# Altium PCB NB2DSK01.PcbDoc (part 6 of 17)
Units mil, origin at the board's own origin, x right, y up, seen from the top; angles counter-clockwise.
Board outline 11815 x 6500.03 mil, 8 copper layers (Top Layer, MidLayer1, MidLayer2, GND, PWR, MidLayer3, MidLayer4, Bottom Layer), stack 74.62 mil thick; 798 components, 1002 nets, 3927 pads, 3182 vias.
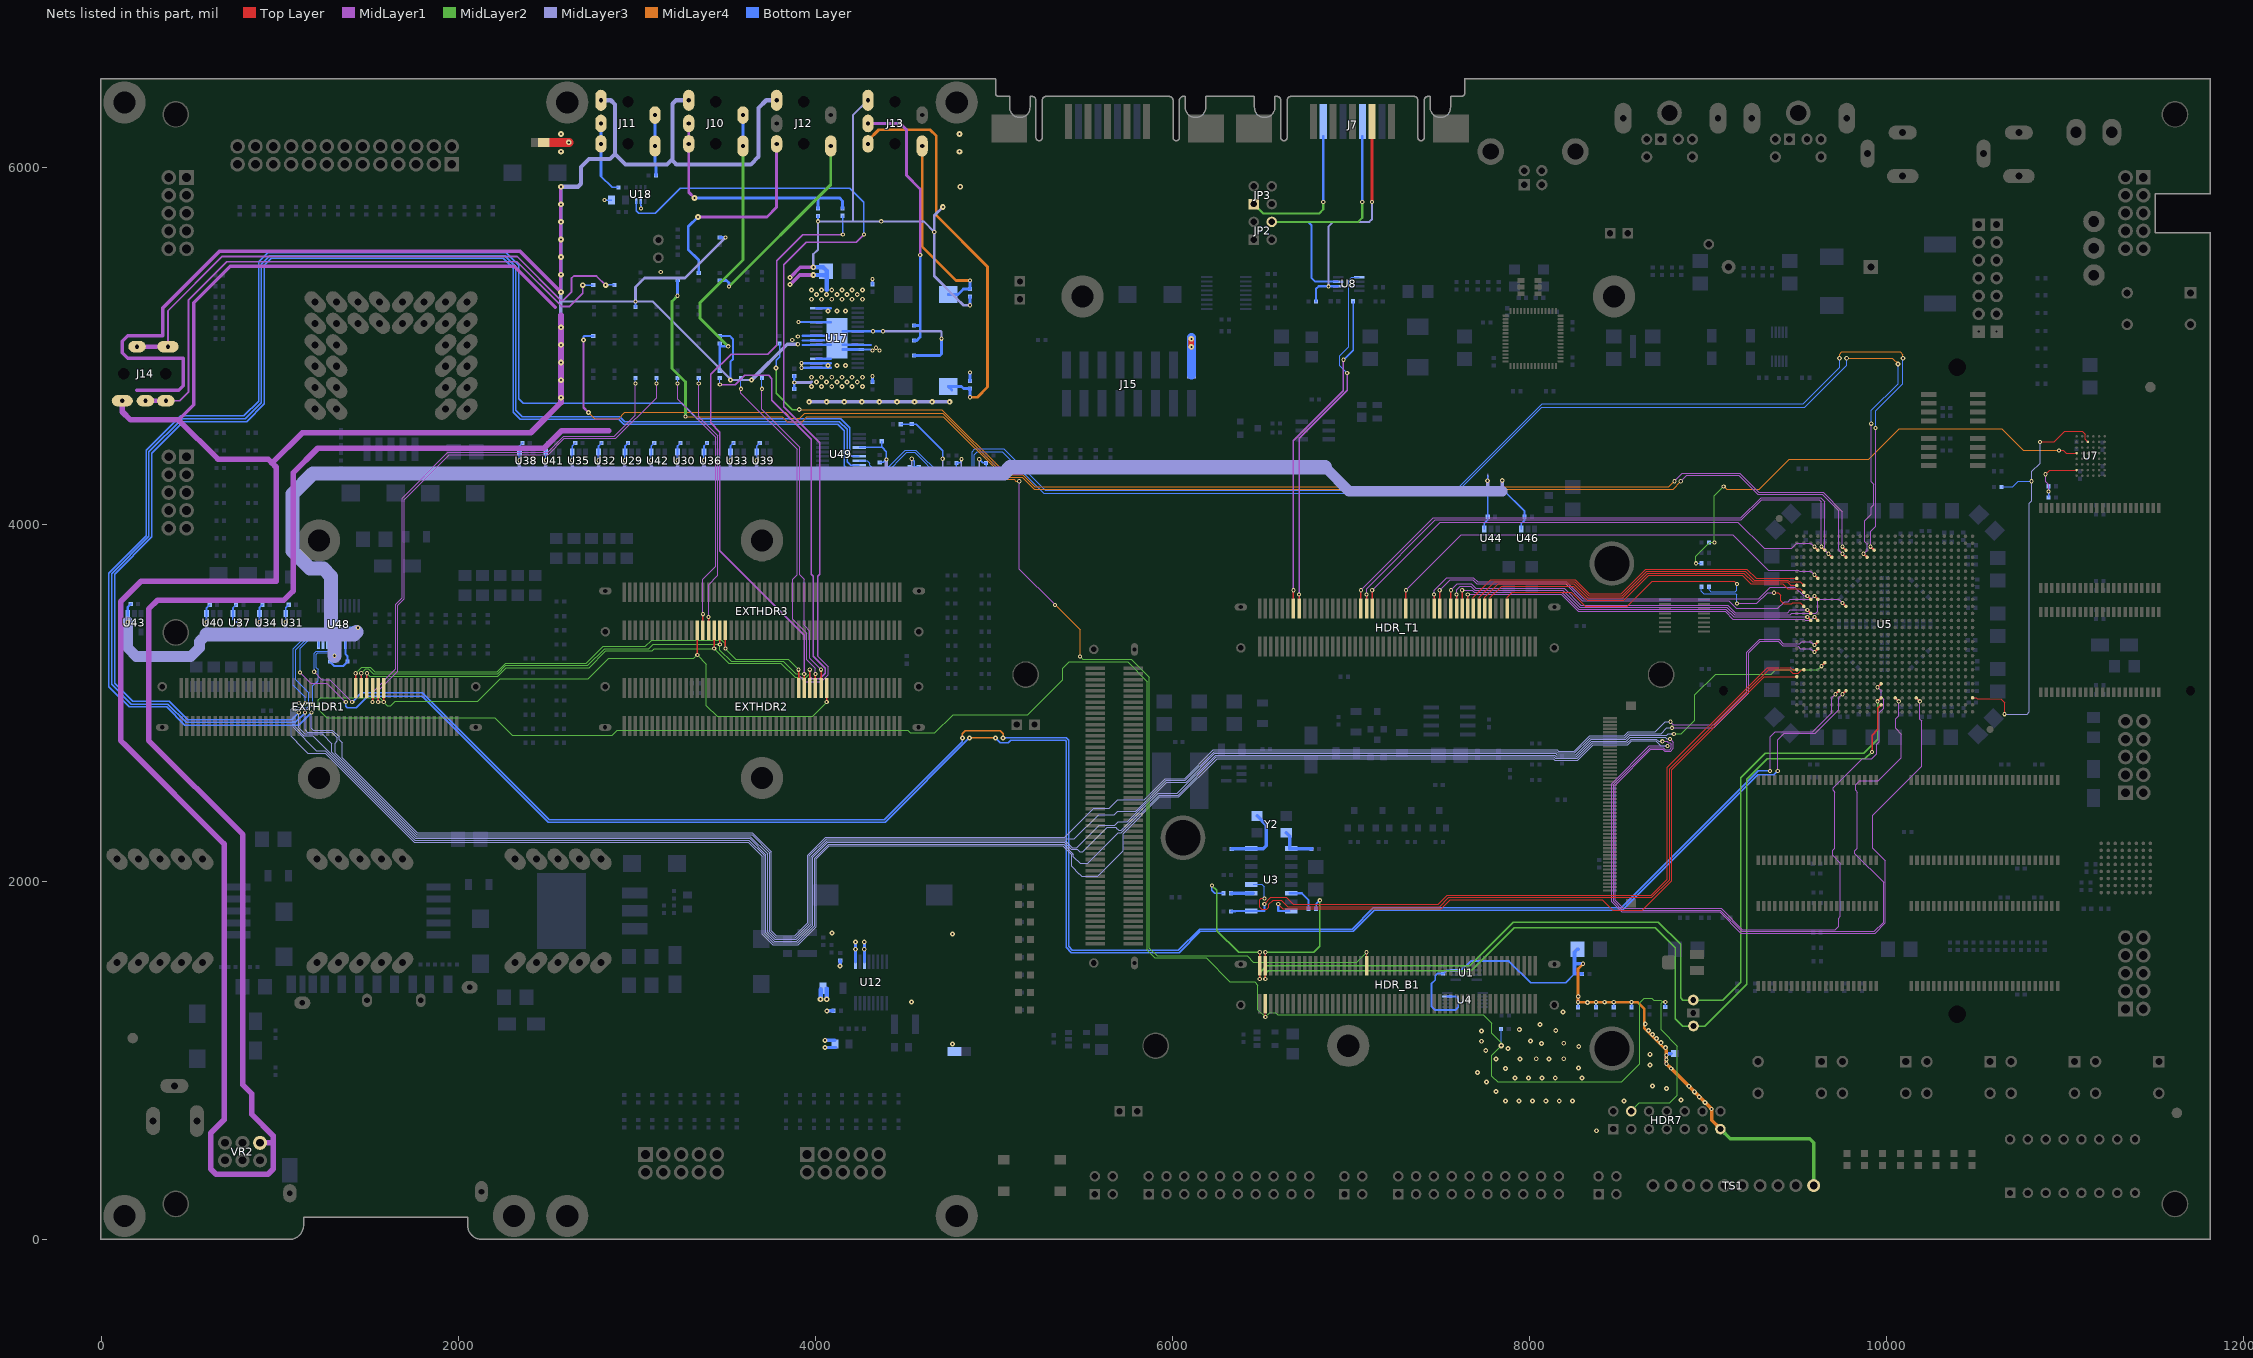
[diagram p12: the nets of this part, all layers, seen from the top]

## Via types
v1: diameter 23.62, hole 11.81, Top Layer to Bottom Layer, tented both sides, 1950 vias
v2: diameter 27.56, hole 11.81, Top Layer to Bottom Layer, tented both sides, 679 vias
v3: diameter 23.62, hole 11.81, Top Layer to Bottom Layer, 194 vias
v4: diameter 31.5, hole 11.81, Top Layer to Bottom Layer, tented both sides, 178 vias
v5: diameter 21.65, hole 11.81, Top Layer to Bottom Layer, tented both sides, 67 vias
v6: diameter 23.62, hole 11.81, Top Layer to Bottom Layer, tented bottom, 53 vias
v7: diameter 26, hole 11.81, Top Layer to Bottom Layer, tented both sides, 21 vias
v8: diameter 26, hole 11.81, Top Layer to Bottom Layer, 13 vias
v9: diameter 28, hole 11.81, Top Layer to Bottom Layer, 8 vias
v10: diameter 25.59, hole 11.81, Top Layer to Bottom Layer, tented both sides, 7 vias
v11: diameter 39.37, hole 11.81, Top Layer to Bottom Layer, tented both sides, 5 vias
v12: diameter 30, hole 11.81, Top Layer to Bottom Layer, 3 vias
v13: diameter 30, hole 11.81, Top Layer to Bottom Layer, tented both sides, 2 vias
v14: diameter 23, hole 11.81, Top Layer to Bottom Layer, tented both sides, 1 vias
v15: diameter 26.56, hole 11.81, Top Layer to Bottom Layer, tented both sides, 1 vias

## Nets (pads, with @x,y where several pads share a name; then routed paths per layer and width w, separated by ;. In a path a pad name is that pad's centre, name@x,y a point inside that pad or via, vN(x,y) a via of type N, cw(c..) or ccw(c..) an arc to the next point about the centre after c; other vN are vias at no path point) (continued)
AD.I2C.SDA: EXTHDR1.27 EXTHDR2.27 EXTHDR3.27 HDR7.4 HDR_B1.3 R7.2 R9.1 | length 15096.9
  Top Layer w5: v1(6519.68,1244.1) HDR_B1.3@6519.68,1318.9
  Top Layer w7.87: v1(1582.68,3007.87) EXTHDR1.27@1582.68,3086.61 ; v1(3338.58,3271.65) EXTHDR3.27@3338.58,3409.45 ; v1(4062.99,3007.87) EXTHDR2.27@4062.99,3086.61
  MidLayer2 w5: v1(4062.99,3007.87) 3984.25,2929.13 3448.82,2929.13 3389.76,2988.19 3389.76,3220.47 v1(3338.58,3271.65) 3318.9,3251.97 2842.52,3251.97 2728.35,3137.8 2236.22,3137.8 2110.24,3011.81 1645.67,3011.81 1622.05,2988.19 1602.36,2988.19 1559.06,3031.5 1228.35,3031.5 1216.54,3019.69 1216.54,2968.5 1264.59,2920.45 2204.68,2920.45 2302.3,2822.84 2862.2,2822.84 2889.76,2850.39 4515.75,2850.39 4531.5,2834.65 4669.29,2834.65 4771.65,2937.01 5188.98,2937.01 5385.83,3133.86 5385.83,3196.85 5421.26,3232.28 5748.03,3232.28 5858.27,3122.05 5858.27,1618.11 5901.58,1574.8 6188.98,1574.8 6321.73,1442.05 6459.52,1442.05 6478.46,1423.11 6478.46,1285.32 v1(6519.68,1244.1) 6543.31,1267.72 6578.74,1267.72 6590.55,1255.91 7738.8,1255.91 7787,1207.71 7787,1154.07 7840.64,1100.43 v4(7840.64,1083.36) ; v4@7840.64,1082 7787,1028.36 7787,913.14 7820.06,880.08 8515.54,880.08 8617,981.54 8617,1324 8642,1349 8684,1349 8694.94,1338.06 8734.08,1338.06 8744.08,1328.06 ; HDR7.4@8568.5,716.54 8614.97,763 8784,763 8826,805 8826,1081.14 8736,1171.14 8736,1319.99 8744.08,1328.06 ; v1(8759.97,1328.06) 8744.08,1328.06
  Bottom Layer w5: v4(7840.64,1083.36) R9.1@7840.64,1177
  Bottom Layer w7.87: R7.2@8759.97,1299.22 v1(8759.97,1328.06)
ADC_GND: C5.2 C6.2 C7.2 C8.2 C9.2 C16.2 C17.2 HDR7.13 NT2.2 TS1.10 U1.7 U4.4 | length 4035.1
  MidLayer2 w19.68: HDR7.13@9068.5,616.54 9123.71,561.33 9568.81,561.33 9590.67,539.47 TS1.10@9590.67,300
  MidLayer4 w15: v1(8299,1542) 8270.97,1513.97 v1(8270.97,1327.04) v1(8370.97,1327.04) v1(8420,1327.04) v1(8470.97,1327.04) v1(8570.97,1327.04) 8602.96,1327.04 8642,1288 8642,1180.22 8765.75,1056.48
  MidLayer4 w19.68: v1(8766,982) v1(8792.43,955.57) v1(9019,729) 9019,666.04 HDR7.13@9068.5,616.54
  MidLayer4 w20: v1@8765.75,982.28 v1(8765.75,1005) v1(8765.75,1030) 8765.75,1056.48
  Bottom Layer w7.87: C5.2@8270.97,1298.19 v1(8270.97,1327.04) ; C6.2@8370.97,1298.19 v1(8370.97,1327.04) ; C7.2@8470.97,1298.19 v1(8470.97,1327.04) ; C8.2@8570.97,1298.19 v1(8570.97,1327.04)
  Bottom Layer w9.84: U4.4@7539.38,1359.06 7585.94,1359.06 7600,1345 7600,1299.34 7583.33,1282.67 7471,1282.67 7450,1303.67 7450,1429.71 7471.31,1451.02 7471.31,1475.45 7483,1487.14 C9.2@7514.54,1487.14 7517.5,1487.14 7535.21,1504.86 U1.7@7586.54,1504.86 7617.86,1504.86 7670,1557 7883.89,1557 8005.41,1435.48 8201.48,1435.48 8251.2,1485.2 ; 8791,1039 NT2.2@8797,1039
  Bottom Layer w19.68: C16.2@8270.89,1623 C16.2@8266.95,1623 8251.2,1607.25 8251.2,1542 ; C17.2@8293.53,1485.2 8251.2,1485.2 8251.2,1542 ; v1(8299,1542) 8251.2,1542
  Bottom Layer w20: v1(8766,982) 8766,1005 8766,1030 8766,1031 8774,1039 8791,1039
  other v2: 8374,607 8982,766 7864.78,773.4 7939.99,773.4 8015.2,773.4 8090.41,773.4 8165.62,773.4 8240.83,773.4 8527.72,773.4 8847,778 8950,796 8923,825 7811.6,826.58 8766,844 8892,856 8687,857 7758.42,879.76 7917.95,902 7993.16,902 8068.37,902 8143.58,902 8294,902 7709,934 7864.77,955.18 8274.22,957.78 8675,975 7811.59,1008.36 7945,1009 8108,1009 8037,1010 8191,1010 8673,1035 7754,1057 7879,1068 8761,1072 8275,1079 8067,1096 8191,1097 8735,1100 7729.76,1108 8005,1110 8711,1123 8688,1147 7729.76,1166.57 8146,1169 8665,1169 7942,1174 8058,1202 8186,1273 8324,1326 8272,1359
  other v15: 8648,1205
AGND: C151.2 C152.1 NT1.1 R69.1 R70.1 U12.9 U12.11 | length 517.6
  Bottom Layer w18: v2(4053.68,1073.45) 4110.31,1073.45 C152.1@4113.68,1073.45 ; v2(4053.68,1113.45) C152.1@4108.68,1113.45 ; v2(4063.68,1278.45) R69.1@4100.5,1278.45 ; v2(4138.68,1528.45) R70.1@4138.68,1560.27 ; U12.9@4224.18,1553.45 4224.18,1623.45 v2@4224.18,1662.95 ; U12.11@4274.18,1553.45 4274.18,1623.45 v2@4274.18,1662.95
  Bottom Layer w25: v4(4028.68,1343.45) C151.2@4028.68,1398.45 ; v4(4063.68,1343.45) 4063.68,1403.45
  other v2: 4768.68,1093.45 4538.68,1328.45 4223.68,1623.45 4273.68,1623.45 4223.68,1663.45 4273.68,1663.45 4768.68,1708.45 4093.68,1713.45
AIN.L: C175.2 EXTHDR3.31 | length 1481.6
  Top Layer w7.87: EXTHDR3.31@3401.57,3409.45 v1(3401.57,3484.25) v1@3401.57,3488.19
  MidLayer1 w5: v1(3346.46,4791.34) 3346.46,4606.3 3452.76,4500 3452.76,3716.54 3401.57,3665.36 v1(3401.57,3484.25)
  Bottom Layer w5: v1(3346.46,4791.34) C175.2@3346.46,4821.85
AIN.R: C185.2 EXTHDR3.29 | length 1529.8
  Top Layer w7.87: EXTHDR3.29@3370.08,3409.45 v1(3370.08,3500)
  MidLayer1 w5: v1(3228.35,4791.34) 3228.35,4704.72 3440.94,4492.13 3440.94,3767.72 3370.08,3696.85 3370.08,3633.86 v1(3370.08,3500)
  Bottom Layer w5: v1(3228.35,4791.34) C185.2@3228.35,4821.85
AOUT_HOST.L: R108.1 U5.D8 | length 8117.3
  Top Layer w7.87: v1(9751.97,3838.58) U5.D8@9771.65,3818.9
  MidLayer1 w5: v1(8846.46,4244.1) 8880.81,4278.45 9170.37,4278.45 9276.82,4172 9639.43,4172 9732.28,4079.14 9732.28,3858.27 v1(9751.97,3838.58)
  MidLayer1 w11.81: v2(2700.79,5035.43) 2700.79,4657.48 v2(2728.35,4629.92)
  MidLayer4 w5: v2(2728.35,4629.92) 2763.78,4594.49 2897.64,4594.49 2933.07,4629.92 3830.71,4629.92 3862.2,4598.43 3913.39,4598.43 3940.95,4625.99 4712.6,4625.99 5070.87,4267.72 5157.48,4267.72 5224.41,4200.79 8803.15,4200.79 v1(8846.46,4244.1)
  Bottom Layer w11.81: v2(2700.79,5035.43) 2700.79,5053.36 2706.01,5058.58 R108.1@2755.91,5058.58
AOUT_HOST.R: R128.1 U5.C8 | length 6821.4
  Top Layer w7.87: v1(9751.97,3877.95) U5.C8@9771.65,3858.27
  MidLayer1 w5: v1(8811.02,4244.1) 8855.38,4288.45 9176.68,4288.45 9209.23,4255.91 9240.16,4224.98 9283.13,4182 9643.57,4182 9751.97,4073.6 v1(9751.97,3877.95)
  MidLayer2 w7.87: v2(3779.53,4877.95) 3779.53,4736.22 3870.08,4645.67 v2(3909.45,4645.67)
  MidLayer4 w5: v2(3909.45,4645.67) 4708.66,4645.67 5074.8,4279.53 5161.42,4279.53 5228.35,4212.6 8779.53,4212.6 v1(8811.02,4244.1)
  Bottom Layer w7.87: v2(3779.53,4877.95) 3779.53,4921.26 3799.21,4940.95 R128.1@3799.21,5016.22
AOUTA.L: C173.2 EXTHDR1.31 | length 2996.2
  Top Layer w7.87: v1(1519.69,3007.87) EXTHDR1.31@1519.69,3086.61
  MidLayer1 w5: v1(1519.69,3007.87) 1519.69,3062.99 1649.61,3192.91 1649.61,3555.12 1685.04,3590.55 1685.04,4149.61 1940.94,4405.51 2500,4405.51 2590.55,4496.06 2874.02,4496.06 2992.13,4614.17 v1(2992.13,4791.34)
  Bottom Layer w5: v1(2992.13,4791.34) C173.2@2992.13,4821.85
AOUTA.R: C184.2 EXTHDR1.29 | length 3032
  Top Layer w7.87: v1(1551.18,3007.87) EXTHDR1.29@1551.18,3086.61
  MidLayer1 w5: v1(1551.18,3007.87) 1551.18,3070.87 1661.42,3181.1 1661.42,3551.18 1696.85,3586.61 1696.85,4141.73 1948.82,4393.7 2503.94,4393.7 2594.49,4484.25 2881.89,4484.25 3110.24,4712.6 v1(3110.24,4791.34)
  Bottom Layer w5: v1(3110.24,4791.34) C184.2@3110.24,4821.85
AOUTB.L: C176.2 EXTHDR2.31 | length 1927.7
  Top Layer w7.87: EXTHDR2.31@4000,3086.61 v1(4000,3165.36)
  MidLayer1 w5: v1(3582.68,4761.81) 3582.68,4737.88 3897.64,4422.92 3897.64,3720.47 3874.02,3696.85 3874.02,3472.44 3952.76,3393.7 3952.76,3244.1 4000,3196.85 v1(4000,3165.36)
  Bottom Layer w5: v1(3582.68,4761.81) C176.2@3582.68,4821.85
AOUTB.R: C186.2 EXTHDR2.29 | length 1873.2
  Top Layer w7.87: EXTHDR2.29@4031.5,3086.61 v1(4031.5,3188.98)
  MidLayer1 w5: v1(3700.79,4761.81) 3700.79,4647.35 3913.39,4434.75 3913.39,3720.47 3937.01,3696.85 3937.01,3437.01 3968.5,3405.51 3968.5,3251.97 v1(4031.5,3188.98)
  Bottom Layer w5: v1(3700.79,4761.81) C186.2@3700.79,4821.85 C186.2@3700.79,4822.84
AOUTC.L: C192.2 EXTHDR1.33 EXTHDR2.33 EXTHDR3.33 | length 5210.3
  Top Layer w7.87: EXTHDR1.33@1488.19,3086.61 v1(1488.19,3169.29) ; v1(3433.07,3307.09) EXTHDR3.33@3433.07,3409.45 ; EXTHDR2.33@3968.5,3086.61 v1(3968.51,3188.98)
  MidLayer1 w5: 3755.8,4698.93 3755.91,4699.04
  MidLayer1 w7.87: v1(3464.57,4785.43) 3551.6,4785.43 3602.87,4836.7 3737.9,4836.7 3755.91,4818.69 3755.91,4699.06 ; 3755.8,4698.93 3976.38,4478.35 3976.38,3724.41 3988.19,3712.6 3988.19,3263.78 4055.12,3196.85 4055.12,3169.29 4023.62,3137.8 3980.32,3137.8 3968.5,3149.61 v1(3968.51,3188.98)
  MidLayer2 w5: v1(1488.19,3169.29) 1503.94,3153.54 2222.08,3153.54 2269.32,3200.79 2732.28,3200.79 2826.77,3295.28 3086.61,3295.28 3098.42,3307.09 v1(3433.07,3307.09) 3515.75,3224.41 3807.09,3224.41 3885.83,3145.67 3948.82,3145.67 3968.51,3165.36 v1(3968.51,3188.98)
  Bottom Layer w5: v1(3464.57,4785.43) C192.2@3464.57,4821.85
AOUTC.MIC: EXTHDR1.37 EXTHDR2.37 EXTHDR3.37 U18.3 | length 7714.6
  Top Layer w7.87: EXTHDR1.37@1425.2,3086.61 v1(1425.2,3169.29) ; v1(3496.06,3307.09) EXTHDR3.37@3496.06,3409.45 ; EXTHDR2.37@3905.51,3086.61 v1(3905.51,3188.98)
  MidLayer1 w5: v1(3905.51,3188.98) 3905.51,3157.48 3940.95,3122.05 4031.5,3122.05 4070.87,3161.42 4070.87,3204.73 4011.81,3263.78
  MidLayer1 w7.87: 4011.81,3263.78 4011.81,3712.6 4023.62,3724.41 4023.62,4460.63 3881.89,4602.36 3822.83,4661.42 3822.83,5456.69 3948.82,5582.68 4228.35,5582.68 v1(4271.65,5625.98)
  MidLayer2 w5: v1(1425.2,3169.29) 1458.91,3203 1505.66,3203 1531.5,3177.17 2217.42,3177.17 2264.66,3224.41 2716.54,3224.41 2811.02,3318.9 3047.24,3318.9 3082.68,3354.33 3476.38,3354.33 3496.06,3334.65 v1(3496.06,3307.09) 3555.12,3248.03 3846.46,3248.03 v1(3905.51,3188.98)
  Bottom Layer w7.87: U18.3@2996.06,5814.96 2996.06,5759.84 3011.81,5744.09 3102.36,5744.09 3244.09,5885.83 4192.91,5885.83 4271.65,5807.09 v1(4271.65,5625.98)
AOUTC.R: C191.2 EXTHDR1.35 EXTHDR2.35 EXTHDR3.35 | length 6241.6
  Top Layer w7.87: EXTHDR1.35@1456.69,3086.62 v1(1456.69,3169.29) ; v1(3464.57,3330.71) EXTHDR3.35@3464.57,3409.45 ; EXTHDR2.35@3937.01,3086.61 v1(3937.01,3165.36)
  MidLayer1 w7.87: v1(3937.01,3165.36) 3937.01,3381.89 3464.57,3854.33 3464.57,4519.69 3413.39,4570.87 3413.39,4842.42 3527.48,4956.52 3734.33,4956.52 3783.46,5005.65 3783.46,5480.32 3929.13,5625.99 v1(4153.54,5625.99)
  MidLayer2 w5: v1(1456.69,3169.29) 1480.32,3192.91 1496.06,3192.91 1523.62,3165.36 2219.75,3165.36 2266.99,3212.6 2724.41,3212.6 2818.9,3307.09 3066.93,3307.09 3090.55,3330.71 v1(3464.57,3330.71) 3464.57,3299.21 3527.56,3236.22 3818.9,3236.22 3889.76,3165.36 v1(3937.01,3165.36)
  Bottom Layer w7.87: v1@4151.97,5627.56 v1(4153.54,5625.99) 4153.54,5674 4151.97,5675.57 C191.2@4151.97,5730.91
AUDIO.AMP_L: C178.2 J14.3 J14.11 | length 3323.6
  MidLayer1 w10: J14.3@362.2,4694.88 440.11,4694.88 488.68,4743.45 488.68,5258.45 703.68,5473.45 2328.68,5473.45 2578.68,5223.45 2623.68,5223.45 2696.85,5296.62 v4(2696.85,5342.52)
  MidLayer1 w23.62: J14.11@236.22,4694.88 J14.11@248.03,4694.88 J14.3@362.2,4694.88
  Bottom Layer w7.87: v4(2696.85,5342.52) C178.2@2755.91,5342.52
AUDIO.AMP_R: C182.2 J14.2 J14.10 | length 3240.4
  MidLayer1 w10: J14.2@374.02,4998.03 374.02,5198.79 678.68,5503.45 2328.68,5503.45 2573.68,5258.45 2588.68,5258.45 2633.68,5303.45 2633.68,5380.98 2646.6,5393.9 2773.42,5393.9 v4(2824.8,5342.52)
  MidLayer1 w23.62: J14.10@188.98,4998.03 J14.10@200.79,4998.03 J14.2@374.02,4998.03
  Bottom Layer w7.87: v4(2824.8,5342.52) 2825.79,5343.5 C182.2@2874.02,5343.5 ; C182.2@2870.68,5338.78 2871.66,5339.76 2873.7,5339.59 C182.2@2874.02,5339.57
AUDIO.HP_L: C177.2 J13.2 R123.2 | length 1093.1
  MidLayer4 w15.75: J13.2@4597.8,6122.05 4597.8,5558.74 4788,5368.54 v1(4866.13,5368.54)
  Bottom Layer w15.75: C177.2@4744.02,5290.38 4798.38,5290.38 4828.38,5320.38 R123.2@4866.13,5320.38 v1(4866.13,5368.54)
AUDIO.HP_R: C180.2 J13.3 R122.2 | length 2291
  MidLayer4 w15.75: J13.3@4294.65,6133.86 4294.65,6152.91 4354.33,6212.6 4641.73,6212.6 4677.17,6177.17 4677.17,5733 4964.57,5445.6 4964.57,4771.65 4907.72,4714.8 v1(4866.13,4714.8)
  Bottom Layer w15.75: C180.2@4744.02,4775.32 4816.68,4775.32 4829.05,4762.95 R122.2@4866.13,4762.95 v1(4866.13,4714.8) ; C180.2@4744.03,4775.3 C180.2@4763.9,4755.43
AUDIO.HP_SENSE: J13.11 R110.1 R111.1 | length 1504.5
  MidLayer1 w15.75: J13.11@4294.65,6240.79 J13.11@4294.65,6248.03 4475.45,6248.03 4510.74,6212.74 4510.74,5957.77 4586.61,5881.89 v1(4586.61,5511.81)
  Bottom Layer w15.75: R110.1@4552.67,5032.72 4567.44,5032.72 4586.61,5051.9 v1(4586.61,5511.81) ; R111.1@4552.67,5117.37 4585.08,5117.37
AUDIO.LIN_L: C192.1 J10.2 J10.10 R134.2 | length 1654.1
  MidLayer2 w15.75: v1(3511.81,5000) 3354.33,5157.48 3354.33,5244.1 3593.86,5483.62 J10.2@3593.86,6122.05
  Bottom Layer w15.75: C192.1@3464.57,4866.14 R134.2@3464.57,5016.22 ; 3467.47,5000 v1(3511.81,5000) ; J10.2@3593.86,6122.05 J10.10@3593.86,6295.28
AUDIO.LIN_R: C191.1 J10.3 J10.11 R133.2 | length 1438
  MidLayer1 w15.75: J10.11@3290.71,6248.03 J10.3@3290.71,6133.86 3290.71,5862.84 v4(3322.83,5830.71)
  Bottom Layer w15.75: J10.3@3290.71,6157.48 J10.3@3290.71,6133.86 J10.3@3290.75,6110.24 ; J10.11@3290.71,6224.41 J10.11@3290.71,6248.03 ; v4(3322.83,5830.71) 4013.28,5830.71 ; R133.2@4014.17,5772.76 4014.17,5829.82 4013.28,5830.71 ; C191.1@4151.97,5772.24 4151.97,5814.66 4135.92,5830.71 4013.28,5830.71
AUDIO.LOUT_L: C190.2 J12.2 | length 1101.3
  MidLayer2 w15.75: v1(3515.75,5334.65) 4085.98,5904.88 J12.2@4085.98,6122.05
  Bottom Layer w15.75: C190.2@3464.57,5369.1 3502.21,5369.1 3515.75,5355.56 v1(3515.75,5334.65)
AUDIO.LOUT_R: C187.1 J12.3 | length 1202.7
  MidLayer1 w15.75: v4(3342.52,5724.41) 3728.35,5724.41 3782.83,5778.9 J12.3@3782.84,6133.86
  Bottom Layer w15.75: v4(3342.52,5724.41) 3287.4,5669.29 3287.4,5542 3346.46,5482.95 C187.1@3346.46,5410.43 ; J12.3@3783.46,6110.24 J12.3@3783.46,6133.86
AUDIO.MIC: C198.1 J11.2 J11.10 | length 340.9
  Bottom Layer w15.75: J11.10@3101.73,6295.28 J11.2@3101.73,6122.05 3101.73,6018.27 3107.28,6012.72 C198.1@3107.28,5956.68
"AUDIO.PARASITE PWR": J11.3 J11.11 R136.2 | length 442.2
  Bottom Layer w7.87: 2798.58,5953.39 2862.2,5889.76 R136.2@2896.14,5889.76
  Bottom Layer w15.75: 2798.58,5953.39 J11.3@2798.58,6133.86 ; J11.3@2798.58,6110.24 J11.3@2798.58,6133.86 ; J11.11@2798.58,6248.03 J11.3@2798.58,6133.86
AUGND: C174.1 C183.2 C193.2 C194.1 C195.1 C196.1 C197.1 J10.1 J11.1 J12.1 J13.1 J14.1 J15.2 NT4.1 pad.0@4120.08,5045.28 R122.1 R123.1 R131.1 R132.2 R133.1 R134.1 U17.1 U17.2 U17.3 U17.6 U17.7 U17.8 U17.11 U17.14 U17.20 U17.23 U17.24 U18.2 VR2.1 | length 36025.4
  Top Layer w30: v4(6105.48,4996.65) v4(6105.48,5041.57)
  Top Layer w50: 2510,6142.3 v4(2618.36,6142.35) v4@2620.13,6142.35
  MidLayer1 w20: 198.68,4753.45 433.68,4753.45 458.68,4778.45 458.68,4933.45 148.68,4933.45 118.68,4963.45 118.68,5028.45 148.68,5058.45 343.68,5058.45 343.68,5213.45 663.68,5533.45 2344.5,5533.45 v4(2574.8,5303.15) v4(2574.8,5401.58) v4(2574.8,5500) v4(2574.8,5598.43) v4(2574.8,5696.85) v4(2574.8,5795.28) v4(2574.8,5893.7) ; 434,4588.77 518.68,4673.45 518.68,5243.45 723.68,5448.45 2313.68,5448.45 2543.68,5218.45 ; v2(3858.27,5346.46) 3911.42,5399.61 v4(3988.19,5399.61) ; v2(3858.27,5385.83) 3915.35,5442.91 v4(3988.19,5442.91)
  MidLayer1 w30: v4(6105.48,4996.65) v4(6105.48,5041.57)
  MidLayer1 w31.5: J14.1@118.11,4694.88 118.11,4633.89 164,4588 434,4588 ; 434,4588.77 434,4588 ; VR2.1@889.76,539.37 963.68,539.37 ; 964.6,539.37 963.68,539.37 ; 2574.8,5174.58 v4(2574.8,5106.3) v4(2574.8,5007.87) v4(2574.8,4909.45) v4(2574.8,4811.02) v4(2574.8,4712.6) 2574.8,4685.04 2405.51,4515.75 1126.39,4515.75 956.82,4346.18 ; 2842.52,4527.56 2579.03,4527.56 2480.6,4429.13 1212.6,4429.13 1074.8,4291.34 1074.8,3629.92 1023.34,3578.45 316.45,3578.45 266,3528 266,2793.06 793.68,2265.37 793.68,863.45 843.68,813.45 843.68,698.45 963.68,578.45 963.68,539.37 ; 434,4588 654,4368 935,4368 956.82,4346.18 ; 956.82,4346.18 980.32,4322.69 980.32,3685.09 224.46,3685.09 109,3569.63 109,2792.57 137.8,2763.78 688.68,2212.89 688.68,668.45 613.68,593.45 613.68,393.45 643.68,363.45 933.68,363.45 963.68,393.45 963.68,539.37
  MidLayer2 w30: v4(6105.48,4996.65) v4(6105.48,5041.57)
  MidLayer4 w30: v4(6105.48,4996.65) v4(6105.48,5041.57)
  MidLayer3 w11.81: v1(4377.95,5084.65) 4703.94,5084.65 4705.71,5082.87 v1(4705.71,5042.77)
  MidLayer3 w12: 2574.8,5250.44 v1(2992.13,5250.51) 3090.07,5250.51 3526.59,4813.99 3529.56,4811.02 v2(3641.73,4811.02) ; v4(3988.19,5442.91) 3988.19,5515.33 4014.17,5541.32 v1(4014.17,5699.88) 4209.89,5699.88 ; J13.1@4294.65,6377.95 4209.89,6293.2 4209.89,5699.88 ; v1(4665.35,5640.55) 4606.02,5699.88 v1(4368.5,5699.88) 4209.89,5699.88
  MidLayer3 w15.75: v1(2992.13,5250.51) 2992.13,5331.7 3042.94,5382.51 3269.01,5382.51 v1(3496.26,5609.76) ; v1(3881.89,4797.24) 3973.43,4797.24 3977.36,4801.18 ; v4(4713.56,5780.51) 4665.35,5732.31 v1(4665.35,5640.55) 4665.35,5393.03 4787.13,5271.25 4828.52,5229.87 v1(4866.13,5229.87)
  MidLayer3 w20: v4(2574.8,4712.6) v4(2574.8,4811.02) v4(2574.8,4909.45) v4(2574.8,5007.87) v4(2574.8,5106.3) 2574.8,5250.44 v4(2574.8,5303.15) v4(2574.8,5401.58) v4(2574.8,5500) v4(2574.8,5598.43) v4(2574.8,5696.85) v4(2574.8,5795.28) v4(2574.8,5893.7) ; v2(3641.73,4811.02) 3842.52,5011.81 v1(3901.57,5011.81) ; v4(3964.57,4688.98) v4(4062.99,4688.98) v4(4161.42,4688.98) v4(4259.84,4688.98) v4(4358.27,4688.98) v4(4456.69,4688.98) v4(4555.12,4688.98) v4(4653.54,4688.98) v4(4751.97,4688.98)
  MidLayer3 w23.62: v4(2574.8,5893.7) 2670,5893.7 2686.7,5910.4 2686.7,6004.7 2731.62,6049.62 2848.76,6049.62 2876.99,6077.84 ; J11.1@2798.58,6377.95 2853.47,6377.95 2876.99,6354.43 2876.99,6077.84 ; J10.1@3290.71,6377.95 3218.47,6377.95 3198.89,6358.37 3198.89,6049.08 ; J12.1@3782.84,6377.95 3724.76,6377.95 3681.93,6335.13 3681.93,6062.08 3638.2,6018.35 3220.95,6018.35 3198.89,6040.41 3198.89,6049.08 ; 2876.99,6077.84 2936.48,6018.35 3168.15,6018.35 3198.89,6049.08
  MidLayer3 w30: v4(6105.48,4996.65) v4(6105.48,5041.57)
  Bottom Layer w7.87: v1(2818.9,5818.9) C197.1@2858.27,5818.9 ; U18.2@3021.65,5814.96 3021.65,5789.37 3023.62,5787.4 v1(3023.62,5771.65)
  Bottom Layer w11.81: v1(3905.51,5135.83) U17.11@4003.94,5135.83 ; 3929.13,5007.87 U17.6@4003.94,5007.87 ; 3929.13,5033.47 U17.7@4003.94,5033.47 ; 3929.13,5059.06 U17.8@4003.94,5059.06 ; U17.24@4236.22,4982.28 v1@4309.06,4982.28 ; U17.23@4236.22,5007.87 4311.02,5007.87 ; U17.20@4236.22,5084.65 v1(4322.83,5084.65) v1(4377.95,5084.65) ; C196.1@4318.9,5347.44 v1(4318.9,5375.99)
  Bottom Layer w12: R132.2@2992.13,5220 v1(2992.13,5250.51) ; R134.1@3464.57,5058.58 3520.01,5058.58 3538.12,5040.48 3538.12,4927.36 3523.62,4912.87 v2(3523.62,4811.02) ; v1(4014.17,5699.88) R133.1@4014.17,5730.39
  Bottom Layer w14.17: v1(3921.26,4879.92) U17.1@4003.94,4879.92 4070.87,4879.92 4086.61,4879.92 ; v1(3921.26,4905.51) U17.2@4003.94,4905.51 4070.87,4905.51 4086.61,4905.51 ; U17.3@4003.94,4931.1 4086.61,4931.1 ; U17.6@4003.94,5007.87 pad.0@4086.61,5007.87 ; U17.7@4003.94,5033.47 pad.0@4086.61,5033.47 ; U17.8@4003.94,5059.06 pad.0@4086.61,5059.06 ; U17.11@4003.94,5135.83 pad.0@4086.61,5135.83 ; U17.14@4003.94,5212.6 4070.87,5212.6 4086.61,5212.6 ; pad.0@4153.54,4982.28 U17.24@4236.22,4982.28 ; pad.0@4153.54,5007.87 U17.23@4236.22,5007.87 ; pad.0@4153.54,5084.65 U17.20@4236.22,5084.65
  Bottom Layer w15.75: R131.1@3464.57,5609.76 v1(3496.26,5609.76) ; C174.1@3881.89,4760.83 v1(3881.89,4797.24) C194.1@3881.89,4833.66 ; C195.1@4318.9,4800.2 v1(4318.9,4832.68) ; C183.2@4552.16,4948.08 4696.59,4948.08 4705.71,4957.19 v1(4705.71,5042.77) ; R122.1@4866.13,4805.32 v1(4866.13,4853.47) ; v1(4866.13,5229.87) R123.1@4866.13,5278.02
  Bottom Layer w23.62: v4(3988.19,5399.61) 4043.31,5399.61 C193.2@4045.28,5397.64 ; v4(3988.19,5442.91) 4043.31,5442.91 4062.01,5424.21 4062.99,5423.23 4062.99,5421.26 4062.99,5314.96
  Bottom Layer w50: J15.2@6105.51,4838.98 v4@6105.51,5049.69
  other v1: 4318.9,4976.38 4358.27,4976.38 4338.58,4992.13 3870.08,5035.43 3901.57,5055.12 3134,5417
  other v2: 3977.36,4775.59 4034.45,4775.59 4091.54,4775.59 4148.62,4775.59 4205.71,4775.59 4262.8,4775.59 4005.91,4801.18 4062.99,4801.18 4120.08,4801.18 4177.17,4801.18 4234.25,4801.18 3977.36,4826.77 4034.45,4826.77 4091.54,4826.77 4148.62,4826.77 4205.71,4826.77 4262.8,4826.77 4070.87,4891.73 4120.09,4891.73 4169.29,4891.73 4070.87,5198.82 4120.09,5198.82 4169.29,5198.82 3977.36,5263.78 4034.45,5263.78 4091.54,5263.78 4148.62,5263.78 4205.71,5263.78 4262.8,5263.78 4005.91,5289.37 4062.99,5289.37 4120.08,5289.37 4177.17,5289.37 4234.25,5289.37 3977.36,5314.96 4034.45,5314.96 4091.54,5314.96 4148.62,5314.96 4205.71,5314.96 4262.8,5314.96
  other v4: 4811.02,5893.7 2574.8,6090.55 4807.09,6090.55 2574.8,6188.98 4807.09,6188.98
BUZZER: HDR_B1.40 R117.1 | length 7271.1
  Top Layer w5: HDR_B1.40@7086.61,1531.5 v1(7086.61,1606.3)
  MidLayer1 w5: v1(5141.73,4244.1) 5141.73,3751.97 v1(5341.81,3551.89)
  MidLayer2 w5: v1(5482.12,3263.11) 5497.77,3247.45 5768.68,3247.45 5870.08,3146.06 5870.08,1629.92 5913.39,1586.61 6417.32,1586.61 6452.76,1551.18 7031.5,1551.18 v1(7086.61,1606.3)
  MidLayer2 w15.75: v1(3228.35,5283.47) 3196.85,5251.97 3196.85,4875.99 3271.65,4801.18 3271.65,4681.1 v1(3271.65,4606.3)
  MidLayer4 w5: v1(3271.65,4606.3) 3814.96,4606.3 3842.52,4578.74 3925.2,4578.74 3952.76,4606.3 4716.54,4606.3 5068.67,4254.16 5113,4254.16 5123.07,4244.1 v1(5141.73,4244.1) ; v1(5341.81,3551.89) 5482.12,3411.59 v1(5482.12,3263.11)
  Bottom Layer w15.75: v1(3228.35,5283.47) R117.1@3228.35,5369.1
CAN#.CAN_H: J7.7 JP2.4 U8.7 | length 1655.2
  MidLayer2 w11.81: JP2.4@6555.12,5696.85 7039.85,5696.85 7062.42,5719.42 v1(7062.42,5808.9)
  Bottom Layer w11.81: JP2.4@6555.12,5696.85 6758.99,5696.85 6779,5676.84 6779,5382 6798.72,5362.28 U8.7@6927,5362.28
  Bottom Layer w15.75: v1(7062.42,5808.9) J7.7@7062.41,6174.79
CAN#.CAN_L: J7.2 R54.2 U8.6 | length 1343.7
  Top Layer w15.75: v1(7116.95,5808.9) J7.2@7117.25,6259.84
  MidLayer3 w11.81: v1(6872.75,5335.85) 6872.75,5669.75 6900,5697 7102,5697 7116.95,5711.95 v1(7116.95,5808.9)
  Bottom Layer w11.81: R54.2@6803.57,5251.05 6803.57,5321.59 6818.67,5336.69 6872.75,5336.69 U8.6@6927,5336.69
CAN.RXD: HDR_T1.14 R53.1 | length 1858.2
  Top Layer w7.87: HDR_T1.14@6677.16,3531.5 v1(6677.16,3633.86)
  MidLayer1 w7.87: v1(6677.16,3633.86) 6677.16,4470.54 6957,4750.37 v1@6957,4925
  Bottom Layer w7.87: v1(6958,4925) 7010.79,4977.79 R53.1@7010.79,5251.96
CAN.TXD: HDR_T1.16 U8.1 | length 2054.2
  Top Layer w7.87: HDR_T1.16@6708.66,3531.5 v1(6708.66,3610.24)
  MidLayer1 w7.87: v1(6708.66,3610.24) 6708.66,4483.82 6978,4753.16 v1(6978,4850)
  Bottom Layer w5: v1(6978,4850) 6936.6,4891.4 6936.6,4946.9 6986.2,4996.5 6986.2,5370.3 7003.77,5387.87 U8.1@7045.11,5387.87
CAN_V+: J7.9 JP3.1 | length 828.2
  MidLayer2 w11.81: JP3.1@6455.12,5796.85 6507.97,5744 6821,5744 6844.31,5767.31 v1(6844.31,5808.9)
  Bottom Layer w15.75: v1(6844.31,5808.9) J7.9@6844.3,6174.79
CCLK: R14.2 U5.AD26 U7.B3 | length 2444
  Top Layer w5: U5.AD26@10480.32,3031.5 10500,3031.5 10506.06,3025.43 10638.19,3025.43 10660,3003.62 v1(10660,2940) ; v1(10858.27,4464.57) 10937.01,4464.57 10996.06,4523.62 11094.49,4523.62 11110.24,4507.87 11110.24,4480.32 U7.B3@11125.98,4464.57
  MidLayer3 w5: v1(10660,2940) 10785.73,2940 10799.21,2953.48 10799.21,4122.05 10811.02,4133.86 v1(10811.02,4244.1) 10811.02,4299.21 10858.27,4346.46 v1(10858.27,4464.57)
  Bottom Layer w5: R14.2@10648.03,4212.21 10704.72,4212.6 10736.22,4244.1 v1(10811.02,4244.1)
CLK_ADJ_X1: C12.1 U3.1 Y2.1 | length 224.8
  Bottom Layer w19.68: Y2.1@6636.62,2275.34 6655.51,2256.44 U3.1@6655.51,2187.01 ; C12.1@6778.54,2185.04 6725.58,2185.04 6723.61,2187.01 U3.1@6665.35,2187.01 U3.1@6657.48,2187.01 ; U3.1@6655.51,2187.01 6657.48,2185.04 U3.1@6657.48,2187.01 ; U3.1@6655.51,2187.01 U3.1@6657.48,2187.01
CLK_ADJ_X2: C13.1 U3.16 Y2.3 | length 391.6
  Bottom Layer w19.68: C13.1@6333.66,2187.01 C13.1@6331.69,2185.04 6369.8,2185.04 6371.77,2187.01 U3.16@6440.95,2187.01 6508.27,2187.01 6524.8,2203.54 6524.8,2319.15 Y2.3@6473.62,2370.34
CLK_FIXED#: R4.2 U3.6 | length 170.7
  Bottom Layer w11.81: U3.6@6655.51,1937.01 U3.6@6665.35,1937.01 6723.58,1937.01 6762.28,1898.3 R4.2@6762.28,1850.39
CLK_PROG#: R3.2 U3.11 | length 122.5
  Bottom Layer w19.68: R3.2@6328.27,1937.01 U3.11@6440.95,1937.01 U3.11@6450.79,1937.01
CLKPLL.CLK_FIXED: HDR_B1.4 R4.1 TP3.1 U5.AE13 | length 6377.4
  Top Layer w7.87: v1(6519.69,1456.69) HDR_B1.4@6519.68,1531.5 v1(6519.69,1606.3) ; v1(9917.32,2728.35) 9917.32,2822.83 9948.82,2854.33 9948.82,2972.44 U5.AE13@9968.5,2992.13
  MidLayer2 w7.87: v1(6519.69,1456.69) 6519.69,1488.19 6535.43,1503.94 7674,1503.94 7915.06,1745 8703,1745 8816,1632 8816,1234 8856.52,1193.48 8981.48,1193.48 9216.54,1428.54 9216.54,2574.8 9330.71,2688.98 9877.95,2688.98 v1(9917.32,2728.35) ; v1(6519.69,1606.3) 6791.34,1606.3 6824.8,1639.76 v1(6824.8,1897.18)
  Bottom Layer w7.87: R4.1@6801.58,1854.33 6804.65,1854.33 R4.1@6804.65,1850.39 6804.65,1877.02 v1(6824.8,1897.18)
CLKPLL.CLK_PROG: HDR_B1.2 R3.1 TP4.1 U5.AD13 | length 6287.3
  Top Layer w7.87: v1(6488.19,1456.69) HDR_B1.2@6488.19,1531.5 v1(6488.19,1606.3) ; v1(9948.82,3011.81) U5.AD13@9968.5,3031.5
  MidLayer2 w7.87: v1(6220.47,1980.32) 6248.03,1952.76 6248.03,1728.35 6370.08,1606.3 v1(6488.19,1606.3) ; v1(6488.19,1456.69) 6488.19,1492.13 6527.56,1531.5 7664.65,1531.5 7908.15,1775 8721,1775 8846,1650 8846,1351 8857.97,1339.03 9081.04,1339.03 9181.1,1439.1 9181.1,2582.68 9318.9,2720.47 9870.08,2720.47 9948.82,2799.21 9948.82,2834.65 ; 9948.82,2834.65 v1(9948.82,3011.81)
  Bottom Layer w7.87: v1(6220.47,1980.32) 6220.47,1952.76 6236.22,1937.01 R3.1@6285.91,1937.01
CLKPLL.CS_N: R5.1 U3.9 U5.Y1 | length 4187.4
  Top Layer w5: v1(6514.17,1876.38) 6551.18,1913.39 6637.8,1913.39 6677.17,1874.02 7488.19,1874.02 7539.37,1925.2 8681.1,1925.2 8771.65,2015.75 8771.65,2641.73 9232.28,3102.36 9330.71,3200.79 9413.39,3200.79 9433.07,3200.79 9460.63,3200.79 9472.44,3188.98 U5.Y1@9496.06,3188.98
  Bottom Layer w5: R5.1@6328.27,1834.65 6354.72,1834.65
  Bottom Layer w11.81: R5.1@6328.27,1834.65 6330.63,1837.01 U3.9@6440.95,1837.01 6514.17,1837.01 v1(6514.17,1876.38)
CLKPLL.DIN: U3.12 U5.Y2 | length 4232.5
  Top Layer w5: v1(6514.4,1908.14) 6497.06,1908.14 6488.19,1899.27 6488.19,1858.27 6500,1846.46 6527.56,1846.46 6539.37,1858.27 6539.37,1874.02 6562.99,1897.64 6610.24,1897.64 6645.67,1862.21 7496.06,1862.21 7547.24,1913.39 8685.04,1913.39 8783.46,2011.81 8783.46,2633.86 9245.23,3095.62 9338.58,3188.98 9413.39,3188.98 9433.07,3188.98 9452.76,3188.98 9472.44,3169.29 9503.94,3169.29 9523.62,3188.98 U5.Y2@9535.43,3188.98
  Bottom Layer w5: U3.12@6450.79,1987.01 6500.15,1987.01 6514.4,1972.76 v1(6514.4,1908.14)
CLKPLL.SCLK: U3.8 U5.AA1 | length 3968.9
  Top Layer w5: v1(6592.13,1876.38) 6618.11,1850.39 7503.94,1850.39 7555.12,1901.58 8405.51,1901.58 8464.57,1842.52 8629.92,1842.52 8795.28,2007.87 8795.28,2629.92 9255.91,3090.55 9314.96,3149.61 9413.39,3149.61 9433.07,3149.61 U5.AA1@9496.06,3149.61
  Bottom Layer w11.81: v1(6592.13,1876.38) 6592.13,1837.01 U3.8@6655.51,1837.01
CONFIG_XCF.PROG: R11.2 R15.2 U7.D1 | length 2751.1
  Top Layer w5: v1(10964.57,4417.32) 10988.19,4417.32 11003.94,4401.58 U7.D1@11062.99,4401.58
  MidLayer2 w5: v1(8931.48,3784.68) 8931.48,3824.18 9009.37,3902.07 v1(9035.09,3902.07) 9035.09,4163.99 v1(9086.6,4215.5)
  MidLayer4 w5: v1(9086.6,4215.5) 9103.12,4198.98 9285.52,4198.98 9452.99,4366.45 9898.68,4366.45 10069.68,4537.45 10643.65,4537.45 10733.35,4447.75 10763.78,4417.32 v1(10964.57,4417.32)
  Bottom Layer w5: v1(8931.48,3784.68) R11.2@8962.1,3784.68 ; R15.2@9004.46,3902.07 v1(9035.09,3902.07)
CONFIG_XCF.TDI: R12.2 R16.2 U7.G1 | length 345.7
  Top Layer w5: v1(10889.76,4283.47) 10913.39,4307.09 U7.G1@11062.99,4307.09
  MidLayer1 w5: v1(10889.76,4283.47) 10889.76,4241.14 10905.98,4224.92 v1@10905.98,4190.65
  Bottom Layer w7.87: R16.2@10905.98,4153.35 v1(10905.98,4187.5) R12.2@10905.98,4216.54
CSGND: C235.2 C236.2 C237.2 C238.2 C239.2 C240.2 C241.2 C242.2 C243.2 C244.2 C245.2 C246.2 C247.2 C248.2 C249.2 C250.2 C252.2 C254.2 C255.2 C256.2 C257.2 C258.1 C259.1 C260.1 C261.1 C262.1 NT6.2 R186.1 R187.1 R188.1 U29.1 U30.1 U31.1 U32.1 U33.1 U34.1 U35.1 U36.1 U37.1 U38.1 U39.1 U40.1 U41.1 U42.1 U43.1 U44.1 U46.1 U48.14 U49.14 | length 14496.2
  MidLayer3 w7.87: 4539.37,4287.4 v1(4539.37,4370.08) ; 4712.6,4291.34 v1(4712.6,4370.08) ; 4817.36,4287.4 v1(4817.36,4368.11) ; 4917.32,4287.4 v1(4917.32,4367.64)
  MidLayer3 w19.68: 590.55,3389.76 v1(590.55,3456.69) ; 771.65,3385.83 v1(771.65,3456.69) ; 885.83,3385.83 v1(885.83,3456.69) ; 1033.46,3391.73 v1(1033.46,3456.69) ; 2342.52,4287.4 v1(2342.52,4362.2) ; 2490.16,4293.31 v1(2490.16,4362.2) ; 2637.8,4287.4 v1(2637.8,4362.2) ; 2785.43,4289.37 v1(2785.43,4362.2) ; 2933.07,4291.34 v1(2933.07,4362.2) ; 3080.71,4289.37 v1(3080.71,4362.2) ; 3228.35,4291.34 v1(3228.35,4362.2) ; 3375.98,4293.31 v1(3375.98,4362.2) ; 3523.62,4287.4 v1(3523.62,4362.2) ; 3671.26,4289.37 v1(3671.26,4362.2) ; 4397.64,4287.4 v1(4397.64,4366.14) ; 7764.76,4189.96 v2(7764.76,4247.05) ; 7846.46,4188.98 v2(7846.46,4248.03)
  MidLayer3 w59.06: 6854.33,4322.83 6988.19,4188.98 7846.46,4188.98
  MidLayer3 w60: v1(148.61,3455.59) 148.61,3311.39 197,3263 502,3263 551,3312 551,3346.28 590.55,3385.83
  MidLayer3 w78.74: 590.55,3385.83 771.65,3385.83 885.83,3385.83 1287.4,3385.83 ; v1(1306,3267) 1306,3371 ; 1430.41,3399.41 1416.83,3385.83 1287.4,3385.83 ; 6854.33,4322.83 5090.55,4322.83 5055.12,4287.4 4917.32,4287.4 3523.62,4287.4 2637.8,4287.4 2342.52,4287.4 1185.04,4287.4 1070.87,4173.23 1070.87,3853.13 1169.33,3754.67 1244.33,3754.67 1287.4,3711.6 1287.4,3385.83
  Bottom Layer w7.87: U49.14@4244.37,4433.46 4373.62,4433.46 4397.64,4409.45 v1(4397.64,4366.14) 4380.91,4349.41 C254.2@4360.24,4349.41 ; 4371.06,4436.02 C257.2@4371.06,4468.5 ; R188.1@4477.87,4562.99 4538.92,4562.99 4563.9,4562.99 4712.6,4414.3 v1(4712.6,4370.08) ; v1(4539.37,4370.08) 4553.1,4356.35 4553.1,4323.82 ; C259.1@4788.39,4303.15 4789.8,4304.57 R187.1@4789.8,4346.93 4811.93,4346.93 4817.36,4352.36 v1(4817.36,4368.11) ; v1(4917.32,4367.64) 4938.03,4346.93 R186.1@4955.22,4346.93 R186.1@4958.66,4346.93 ; C258.1@4955.71,4303.15 R186.1@4955.71,4345.47 ; v2@7765,4247.28 NT6.2@7765,4274.25
  Bottom Layer w10: v1(590.55,3456.69) U40.1@590.55,3503.94 590.55,3536.32 C245.2@607.38,3553.15 ; C242.2@755.02,3553.15 738.19,3536.32 U37.1@738.19,3503.94 738.19,3470.47 751.97,3456.69 v1(771.65,3456.69) ; v1(885.83,3456.69) U34.1@885.83,3503.94 885.83,3536.32 C244.2@902.66,3553.15 ; v1(1033.46,3456.69) U31.1@1033.46,3503.94 1033.46,3536.32 C236.2@1050.3,3553.15 ; v1(2342.52,4362.2) U38.1@2342.52,4409.45 2342.52,4441.83 C252.2@2359.35,4458.66 ; v1(2490.16,4362.2) U41.1@2490.16,4409.45 2490.16,4441.83 C250.2@2506.99,4458.66 ; v1(2637.8,4362.2) U35.1@2637.8,4409.45 2637.8,4441.83 C248.2@2654.63,4458.66 ; v1(2785.43,4362.2) U32.1@2785.43,4409.45 2785.43,4441.83 C243.2@2802.26,4458.66 ; v1(2933.07,4362.2) U29.1@2933.07,4409.45 2933.07,4439.96 2950.84,4457.73 C241.2@2951.77,4458.66 ; v1(3080.71,4362.2) U42.1@3080.71,4409.45 3080.71,4441.83 C249.2@3097.54,4458.66 ; v1(3228.35,4362.2) U30.1@3228.35,4409.45 3228.35,4441.83 C238.2@3245.18,4458.66 ; v1(3375.98,4362.2) U36.1@3375.98,4409.45 3375.98,4441.83 C247.2@3392.82,4458.66 ; v1(3523.62,4362.2) U33.1@3523.62,4409.45 3523.62,4441.83 C239.2@3540.45,4458.66 ; v1(3671.26,4362.2) U39.1@3671.26,4409.45 3671.26,4441.83 C237.2@3688.09,4458.66 ; C261.1@4539.37,4323.82 4553.1,4323.82 C262.1@4578.74,4323.82 ; U44.1@7746.06,3976.38 7746.06,4009.84 7764.76,4028.54 C235.2@7764.76,4045.28 v2(7764.76,4247.05) ; v2(7846.46,4248.03) 7846.46,4200.79 7971.46,4075.79 C240.2@7971.46,4045.28 7971.46,4026.57 7952.76,4007.87 U46.1@7952.76,3976.38
  Bottom Layer w12: v1(148.61,3455.59) U43.1@148.61,3502.9 148.61,3539.9 C246.2@165.55,3556.84 ; v1(1306,3267) 1292,3267 1281.42,3256.42 C255.2@1281.42,3234.1 1305.52,3210 1355.76,3210 C256.2@1379.84,3234.09 1379.84,3265.16 1367.5,3277.5 U48.14@1367.5,3342.24 1367.5,3406.5 1384.76,3423.76 v2(1439,3423.76)
CSSPI_CS1: U5.C12 U49.17 | length 7751.2
  Top Layer w7.87: v1(9909.45,3877.95) U5.C12@9929.13,3858.27
  MidLayer1 w5: v1(9909.45,3877.95) 9909.45,3964.57 9937.01,3992.13 v1(9937.01,4543.31)
  MidLayer4 w5: v2(9736.22,4933.07) 9736.22,4956.69 9748.03,4968.5 10074.8,4968.5 10090.55,4952.76 v2(10090.55,4933.07)
  Bottom Layer w5: U49.17@4244.37,4358.46 4291.14,4358.46 4303.15,4346.46 4303.15,4334.65 4326.77,4311.02 4397.64,4311.02 4503.94,4417.32 4562.99,4417.32 4700.79,4279.53 4870.08,4279.53 4877.95,4287.4 4877.95,4409.45 4893.7,4425.2 5055.12,4425.2 5287.4,4192.91 7586.91,4192.91 8071.17,4677.17 9531.5,4677.17 9736.22,4881.89 v2(9736.22,4933.07) ; v1(9937.01,4543.31) 9937.01,4637.8 10090.55,4791.34 v2(10090.55,4933.07)
CSSPI_CS2: U5.AC7 U48.17 | length 11375.4
  Top Layer w7.87: v1(9712.6,3051.18) U5.AC7@9732.28,3070.87
  MidLayer1 w5: v1(1192.91,3177.17) 1236.22,3133.86 1279.53,3133.86 v1(1405.51,3007.87) ; v1(9346.46,2622.05) 9346.46,2813.91 9375,2842.45 9586.55,2842.45 9692.91,2948.82 9692.91,3031.5 v1(9712.6,3051.18)
  MidLayer4 w7.87: v2(4822.83,2807.09) 4822.83,2830.71 4838.58,2846.46 5035.43,2846.46 5051.18,2830.71 v2(5051.18,2807.09)
  Bottom Layer w5: v1(1192.91,3177.17) 1192.91,3281.91 1203.93,3292.93 1287.43,3292.93 1292.5,3298 U48.17@1292.5,3342.24
  Bottom Layer w7.87: v1(1405.51,3007.87) 1456.69,3059.06 1797.73,3059.06 2509.27,2347.52 4384.43,2347.52 4822.83,2785.92 v2(4822.83,2807.09) ; v2(5051.18,2807.09) 5404.91,2807.09 5418,2794 5418,1639 5439,1618 6032.86,1618 6151.18,1736.31 7006.28,1736.31 7125.28,1855.31 8514.27,1855.31 9281.01,2622.05 v1(9346.46,2622.05)
CSSPI_DIN: U5.U4 U49.18 | length 18989.3
  Top Layer w7.87: v1(9594.49,3287.4) U5.U4@9614.17,3307.09
  MidLayer1 w5: v1(8796.8,2863.4) 9030.36,2863.4 9226.22,3059.26 9226.22,3282.94 9291.54,3348.27 9393.5,3348.27 9418.82,3322.94 9499.9,3322.94 9503.94,3318.9 9515.75,3307.09 9574.8,3307.09 v1(9594.49,3287.4)
  MidLayer3 w5: v1(1141.73,2948.82) 1141.73,2853 1155.03,2839.7 1290.22,2839.7 1322,2807.92 1322,2791.3 1315.32,2784.63 1315.32,2783.32 1310,2778 1310,2722.28 1768.5,2263.78 3645.08,2263.78 3744,2164.86 3744,1722.37 3777.39,1688.98 3888.16,1688.98 3966,1766.82 3966,2145.86 4062.11,2241.97 5450.63,2241.97 5586.61,2377.95 5673.23,2377.95 5692.58,2397.3 5792.72,2397.3 5964.47,2569.06 6071.39,2569.06 6232.49,2730.16 8149.3,2730.16 8156.86,2722.6 8253.74,2722.6 8339.94,2808.8 8533.8,2808.8 8555.71,2830.71 8736.05,2830.71 8768.74,2863.4 v1(8796.8,2863.4)
  Bottom Layer w7.87: v1@1142,2949.09 1086.61,2893.7 476.38,2893.7 374.02,2996.06 169.29,2996.06 59.06,3106.3 59.06,3726.85 267.72,3935.51 267.72,4409.45 452.76,4594.49 807.09,4594.49 897.64,4685.04 897.64,5460.63 944.88,5507.87 2259.84,5507.87 2322.83,5444.88 2322.83,4641.73 2358.27,4606.3 2905.51,4606.3 2933.07,4578.74 4133.86,4578.74 4177.17,4535.43 4177.17,4354.33 4198.03,4333.46 U49.18@4244.37,4333.46
CSSPI_DIN2: U5.AD15 U48.18 | length 14318
  Top Layer w7.87: U5.AD15@10047.24,3031.5 v1(10066.93,3011.81)
  MidLayer1 w5: v1(8743.1,2787.8) 8770.5,2787.8 8777.39,2780.91 8786.29,2780.91 8794.4,2772.8 8794.4,2751.6 8784.3,2741.5 8760.2,2741.5 8749.5,2752.2 8675.24,2752.2 8469.7,2546.66 8469.7,1892.64 8519.34,1843 9068.4,1843 9187.6,1723.8 9930.16,1723.8 9982.2,1775.84 9982.2,1997.6 9821,2158.8 9821,2175.4 9835.7,2190.1 9835.7,2503.1 9826.3,2512.5 9826.3,2545.5 9848.7,2567.9 9953.7,2567.9 10081.9,2696.1 10081.9,2827.55 10049.37,2860.08 10049.37,2913.18 10066.93,2930.74 v1(10066.93,3011.81)
  MidLayer3 w5: v1(1142,3000.6) 1119.6,2978.2 1091.9,2978.2 1075.4,2961.7 1075.4,2865.4 1205.2,2735.6 1254.26,2735.6 1756.08,2233.78 3627.94,2233.78 3713,2148.72 3713,1710.94 3764.97,1658.98 3900.58,1658.98 3996,1754.39 3996,2133.43 4074.54,2211.97 5389.67,2211.97 5445.29,2156.35 5445.29,2141.41 5482.2,2104.5 5525.7,2104.5 5695.8,2274.6 5712.44,2274.6 5924.34,2486.5 6031.26,2486.5 6244.92,2700.16 8136.87,2700.16 ; 8136.2,2700.16 8143.76,2692.6 8266.17,2692.6 8352.37,2778.8 8546.53,2778.8 8568.44,2800.71 8709.19,2800.71 8722.1,2787.8 v1(8743.1,2787.8)
  Bottom Layer w5: v1(1142,3000.6) 1142,3036 1075,3103 1075,3305 1180,3410 1251,3410 1267.5,3393.5 U48.18@1267.5,3342.24
CSSPI_DOUT: U5.W5 U49.19 | length 18846.3
  Top Layer w7.87: v1(9633.86,3208.66) U5.W5@9653.54,3228.35
  MidLayer2 w5: v1(8807.4,2829.5) 8849.99,2829.5 8926,2905.51 8926,3048 9040.89,3162.89 9351.87,3162.89 9377.95,3188.98 9614.17,3188.98 v1(9633.86,3208.66)
  MidLayer3 w5: v1(1106.3,2948.82) 1106.3,2862.79 1139.39,2829.7 1237.23,2829.7 1291.33,2775.6 1291.33,2726.82 1764.36,2253.78 3636.22,2253.78 3733,2157 3733,1719.23 3773.25,1678.98 3892.3,1678.98 3976,1762.68 3976,2141.72 4066.25,2231.97 5397.95,2231.97 5437.01,2192.91 5464.57,2192.91 5590.55,2318.9 5677.17,2318.9 5694.77,2336.5 5746.06,2336.5 5968.61,2559.06 6075.53,2559.06 6236.63,2720.16 8145.16,2720.16 8152.72,2712.6 8257.88,2712.6 8344.08,2798.8 8537.94,2798.8 8559.85,2820.71 8768.25,2820.71 8777.04,2829.5 v1(8807.4,2829.5)
  Bottom Layer w7.87: v1(1106.3,2948.82) 1066.93,2909.45 484.25,2909.45 381.89,3011.81 177.17,3011.81 74.8,3114.17 74.8,3724.39 283.46,3933.05 283.46,4401.57 460.63,4578.74 814.96,4578.74 913.39,4677.17 913.39,5452.76 952.76,5492.13 2251.97,5492.13 2307.09,5437.01 2307.09,4629.92 2346.46,4590.55 2897.64,4590.55 2925.2,4562.99 4125.98,4562.99 4161.42,4527.56 4161.42,4330.71 4183.66,4308.46 U49.19@4244.37,4308.46
CSSPI_DOUT2: U5.AD18 U48.19 | length 14368.6
  Top Layer w7.87: U5.AD18@10165.35,3031.5 v1(10185.04,3011.81)
  MidLayer1 w5: v1(8772.6,2762.2) 8671.1,2762.2 8459.7,2550.8 8459.7,1888.5 8515.2,1833 9064.2,1833 9183.4,1713.8 9934.3,1713.8 9992.2,1771.7 9992.2,2118.1 9921.3,2189 9921.3,2373.5 10194.72,2646.92 10194.72,2902.58 10185.04,2912.26 v1(10185.04,3011.81)
  MidLayer3 w5: v1(1109.3,3001.8) 1095.7,2988.2 1084.8,2988.2 1063.6,2967 1063.6,2815.3 1093.87,2785.03 1093.87,2783.66 1156.1,2721.42 1254.29,2721.42 1751.94,2223.78 3623.79,2223.78 3703,2144.57 3703,1706.8 3760.83,1648.98 3904.73,1648.98 4006,1750.25 4006,2129.29 4078.68,2201.97 5385.53,2201.97 5435.29,2152.21 5435.29,2088.89 ; 5434.65,2088.25 5475.45,2047.45 5476.73,2047.45 5491.08,2033.1 5580.1,2033.1 5722.98,2175.98 5722.98,2271 5928.48,2476.5 6035.4,2476.5 6249.06,2690.16 8132.06,2690.16 8139.62,2682.6 8270.31,2682.6 8356.51,2768.8 8550.68,2768.8 8572.58,2790.71 8705.05,2790.71 8733.56,2762.2 v1(8772.6,2762.2)
  Bottom Layer w5: v1(1109.3,3001.8) 1134.1,2977 1154,2977 1163,2986 1163,3058.96 1089.87,3132.09 1089.87,3301.67 1185.33,3397.13 1233.13,3397.13 1242.5,3387.75 U48.19@1242.5,3342.24
CSSPI_EOC1: U5.D11 U49.20 | length 7686.8
  Top Layer w7.87: v1(9870.08,3838.58) U5.D11@9889.76,3818.9
  MidLayer1 w5: v1(9870.08,3838.58) 9889.76,3858.27 9889.76,3893.7 9877.95,3905.51 9877.95,4023.62 9913.39,4059.06 9913.39,4098 9927.01,4111.62 9927.01,4227.38 9913.39,4241 v1(9913.39,4566.93)
  MidLayer4 w5: v2(9775.59,4933.07) 10031.5,4933.07 v2(10062.99,4901.57)
  Bottom Layer w5: U49.20@4244.37,4283.46 4389.76,4283.46 4511.81,4405.51 4555.12,4405.51 4692.91,4267.72 4874.02,4267.72 4889.76,4283.46 4889.76,4393.7 4905.51,4409.45 5047.24,4409.45 5279.53,4177.17 7586.61,4177.17 8066.93,4657.48 9539.37,4657.48 9775.59,4893.7 v2(9775.59,4933.07) ; v1(9913.39,4566.93) 9913.39,4641.73 10062.99,4791.34 v2(10062.99,4901.57)
CSSPI_EOC2: U5.AC8 U48.20 | length 11520.7
  Top Layer w7.87: v1(9751.97,3051.18) U5.AC8@9771.65,3070.87
  MidLayer1 w5: v1(1114.17,3173.23) 1173.23,3114.17 1263.78,3114.17 v1(1370.08,3007.87) ; v1(9389.76,2622.05) 9389.76,2797.22 9425,2832.45 9600.17,2832.45 9732.28,2964.57 9732.28,3031.5 v1(9751.97,3051.18)
  MidLayer4 w7.87: v2(4862.2,2807.09) v2(5007.87,2807.09)
  Bottom Layer w5: v1(1114.17,3173.23) 1114.17,3307.76 1179.41,3373 1214,3373 1217.5,3369.5 U48.20@1217.5,3342.24
  Bottom Layer w7.87: U48.20@1218,3316 U48.20@1218,3342.24 ; v1(1370.08,3007.87) 1370.08,2984.25 1377.95,2976.38 1429.13,2976.38 1492.13,3039.37 1799.21,3039.37 2503.94,2334.65 4389.76,2334.65 v2(4862.2,2807.09) ; v2(5007.87,2807.09) 5033.96,2781 5081,2781 5094.21,2794.21 5399.58,2794.21 5405.13,2788.67 5405.13,1633.67 5433.67,1605.13 6038.2,1605.13 6156.51,1723.44 7011.61,1723.44 7130.61,1842.43 8519.6,1842.43 9277.37,2600.2 9367.92,2600.2 v1(9389.76,2622.05)
CSSPI_SCLK: U5.T4 U49.16 | length 18980.1
  Top Layer w7.87: v1(9594.49,3326.77) U5.T4@9614.17,3346.46
  MidLayer1 w5: v1(8788.5,2897.3) 8804.84,2880.96 9033.77,2880.96 9216.22,3063.4 9216.22,3287.09 9287.4,3358.27 9397.64,3358.27 9421.26,3334.65 9511.81,3334.65 9523.62,3346.46 9574.8,3346.46 v1(9594.49,3326.77)
  MidLayer3 w5: v1(1177.17,2948.82) 1177.17,2861 1188.47,2849.7 1294.36,2849.7 1332,2812.06 1332,2798 1351,2779 1351,2695.43 1770.84,2275.59 3647.41,2275.59 3754,2169 3754,1726.51 3781.54,1698.98 3884.02,1698.98 3956,1770.96 3956,2150 4057.97,2251.97 5397.64,2251.97 5559.06,2413.39 5645.67,2413.39 5692.78,2460.5 5841.77,2460.5 5960.33,2579.06 6067.24,2579.06 6228.35,2740.16 8153.44,2740.16 8161,2732.6 8249.6,2732.6 8335.8,2818.8 8529.66,2818.8 8551.57,2840.71 8704.1,2840.71 8760.69,2897.3 v1(8788.5,2897.3)
  Bottom Layer w7.87: v1(1177.17,2948.82) 1106.3,2877.95 468.5,2877.95 366.14,2980.32 157.48,2980.32 43.31,3094.49 43.31,3729.31 251.97,3937.97 251.97,4417.32 444.88,4610.24 799.21,4610.24 881.89,4692.91 881.89,5472.44 933.07,5523.62 2267.72,5523.62 2338.58,5452.76 2338.58,4707.5 2363.58,4682.5 3250.57,4682.5 3338.58,4594.49 4141.73,4594.49 4192.91,4543.31 4192.91,4392.91 4202.36,4383.46 U49.16@4244.37,4383.46
CSSPI_SCLK2: U5.AB13 U48.16 | length 13897.5
  Top Layer w7.87: v1(9948.82,3090.55) U5.AB13@9968.5,3110.24
  MidLayer1 w5: v1(8786.1,2801.1) 8805.6,2781.6 8805.6,2748 8789.1,2731.5 8756.06,2731.5 8745.36,2742.2 8679.38,2742.2 8479.7,2542.52 8479.7,1896.78 8523.48,1853 9072.54,1853 9191.74,1733.8 9712.4,1733.8 9730.1,1751.5 9730.1,1797.1 9740.1,1807.1 9740.1,2105.2 9696.4,2148.9 9696.4,2176.73 9709.4,2189.73 9709.4,2501.84 9705.93,2505.31 9705.93,2506.98 9700.39,2512.52 9700.39,2528.77 9862.92,2691.3 9915.4,2691.3 9942.62,2718.52 9942.62,2771 9957.01,2785.39 9957.01,2948.41 9982.7,2974.1 9982.7,3022.2 9968.3,3036.6 9968.3,3071.07 v1(9948.82,3090.55)
  MidLayer3 w5: v1(1185,2994) 1159.2,2968.2 1096.6,2968.2 1086,2957.6 1086,2868.94 1135.24,2819.7 1184.3,2819.7 1760.22,2243.78 3632.08,2243.78 3723,2152.86 3723,1715.09 3737.84,1700.24 3769.11,1668.98 3896.44,1668.98 3986,1758.53 3986,2137.57 4070.4,2221.97 5393.81,2221.97 5433.28,2182.5 5467.3,2182.5 5481.5,2168.3 5497.4,2168.3 5634.4,2305.3 5682.2,2305.3 5688.16,2299.34 5689.43,2299.34 5700.07,2288.7 5712.4,2288.7 5920.2,2496.5 6027.12,2496.5 6240.77,2710.16 8141.02,2710.16 8148.57,2702.6 8262.03,2702.6 8348.23,2788.8 8542.39,2788.8 8564.3,2810.71 8758.1,2810.71 8767.71,2801.1 v1(8786.1,2801.1)
  Bottom Layer w5: v1(1185,2994) 1185,3098.39 1215,3128.39 1215,3191 1205.79,3200.21 1205.79,3275.79 1212.93,3282.93 1295.09,3282.93 1300.16,3288 1312,3288 1317.5,3293.5 U48.16@1317.5,3342.24
DAU_CLK.FPGA_CLK1: HDR_T1.90 R17.2 | length 1675.9
  Top Layer w5: HDR_T1.90@7874.02,3531.5 7874.02,3594.49 7901.58,3622.05 8232.28,3622.05 8311.02,3543.31 8545.53,3543.31 8686.95,3684.72 9145.28,3684.72 v1(9161,3669)
  Bottom Layer w5: R17.2@9004.46,3653.54 9004.46,3636 9015.46,3625 9151,3625 9161,3635 v1(9161,3669)
DAU_FPGA_CLK1: R17.1 U5.L2 | length 733.5
  Top Layer w5: v1(9368,3620) 9392,3620 9406,3606 9406,3576.13 9423.68,3558.45 9468.68,3558.45 9473.68,3563.45 9515.29,3563.45 U5.L2@9535.43,3543.31
  MidLayer1 w5: v1(9161,3560) 9273,3560 9333,3620 v1(9368,3620)
  Bottom Layer w5: R17.1@8962.1,3653.54 8962.1,3627.9 8975,3615 9154,3615 9161,3608 v1(9161,3560)
DAU_JTAG.HARD.TCK: HDR_T1.72 U5.L8 | length 2449.2
  Top Layer w7.87: HDR_T1.72@7590.55,3531.5 v1(7590.55,3610.24) ; v1(9751.97,3562.99) U5.L8@9771.65,3543.31
  MidLayer1 w5: v1(7590.55,3610.24) 7590.55,3637.8 7610.24,3657.48 7669.29,3657.48 7692.91,3633.86 8185.04,3633.86 8279.53,3539.37 9104.27,3539.37 9147.58,3496.06 9413.39,3496.06 9433.07,3496.06 9460.63,3496.06 9468.5,3503.94 9602.36,3503.94 9614.17,3515.75 9614.17,3574.8 9622.05,3582.68 9732.28,3582.68 v1(9751.97,3562.99)
DAU_JTAG.HARD.TDI: HDR_T1.78 U5.G1 | length 2025.2
  Top Layer w5: HDR_T1.78@7685.04,3531.5 7685.04,3594.49 7783.47,3692.91 8255.91,3692.91 8334.65,3614.17 8513.4,3614.17 8650.68,3751.45 9217.05,3751.45 9267.72,3700.79 U5.G1@9496.06,3700.79
DAU_JTAG.HARD.TDO: HDR_T1.54 U5.G4 | length 2615.8
  Top Layer w7.87: HDR_T1.54@7307.09,3555.12 v1(7307.09,3633.86) ; v1(9594.49,3720.47) U5.G4@9614.17,3700.79
  MidLayer1 w5: v1(7307.09,3633.86) 7618.11,3944.88 9137.8,3944.88 9336.22,3746.45 9505.26,3746.45 9511.55,3740.16 9574.8,3740.16 v1(9594.49,3720.47)
DAU_JTAG.HARD.TMS: HDR_T1.70 U5.M3 | length 2214.2
  Top Layer w7.87: HDR_T1.70@7559.06,3531.5 v1(7559.06,3633.86) ; v1(9555.12,3523.62) U5.M3@9574.8,3503.94
  MidLayer1 w5: v1(7559.06,3633.86) 7594.38,3669.19 7673.33,3669.19 7696.85,3645.67 8192.91,3645.67 8287.4,3551.18 9109.17,3551.18 9152.47,3507.87 9413.39,3507.87 9433.07,3507.87 9444.88,3507.87 9460.63,3523.62 v1(9555.12,3523.62)
DAU_JTAG.SOFT.TCK: HDR_T1.82 U5.H1 | length 1960.3
  Top Layer w5: HDR_T1.82@7748.03,3531.5 7748.03,3594.49 7822.84,3669.29 8248.03,3669.29 8326.77,3590.55 8521.78,3590.55 8660.68,3729.45 9199.68,3729.45 9248.35,3680.79 9441.9,3680.79 9461.27,3661.42 U5.H1@9496.06,3661.42
DAU_JTAG.SOFT.TDI: HDR_T1.84 U5.J2 | length 1975.4
  Top Layer w5: HDR_T1.84@7779.53,3531.5 7779.53,3594.49 7842.52,3657.48 8244.09,3657.48 8322.83,3578.74 8527.88,3578.74 8667.59,3718.45 9191,3718.45 9238.66,3670.79 9417.42,3670.79 9446.47,3641.73 9515.75,3641.73 U5.J2@9535.43,3622.05
DAU_JTAG.SOFT.TDO: HDR_T1.76 U5.N4 | length 2116
  Top Layer w7.87: HDR_T1.76@7653.54,3531.5 v1(7653.54,3610.24) ; v1(9594.49,3484.25) U5.N4@9614.17,3464.57
  MidLayer1 w5: v1(7653.54,3610.24) 8177.17,3610.24 8271.65,3515.75 9094.49,3515.75 9137.8,3472.44 9413.39,3472.44 9433.07,3472.44 9535.43,3472.44 9543.31,3464.57 9574.8,3464.57 v1(9594.49,3484.25)
DAU_JTAG.SOFT.TMS: HDR_T1.80 U5.H2 | length 2040.3
  Top Layer w5: HDR_T1.80@7716.54,3531.5 7716.54,3594.49 7803.15,3681.1 8251.97,3681.1 8330.71,3602.36 8517.59,3602.36 8655.68,3740.45 9208.37,3740.45 9258.03,3690.79 9446.05,3690.79 9455.73,3681.1 9515.75,3681.1 U5.H2@9535.43,3661.42
DAU_PROG.CCLK: HDR_T1.66 U5.K4 | length 2348.5
  Top Layer w7.87: HDR_T1.66@7496.06,3531.5 v1(7496.06,3633.86) ; v1(9594.49,3602.36) U5.K4@9614.17,3582.68
  MidLayer1 w5: v1(7496.06,3633.86) 7555.12,3692.91 7681.1,3692.91 7704.72,3669.29 8200.79,3669.29 8295.28,3574.8 9113.83,3574.8 9156.18,3532.45 9389.57,3532.45 9427.98,3570.87 9448.82,3570.87 9460.63,3582.68 9574.8,3582.68 v1(9594.49,3602.36)
DAU_PROG.DIN: HDR_T1.64 U5.K3 | length 2345.9
  Top Layer w7.87: HDR_T1.64@7464.57,3531.5 v1(7464.57,3610.24) ; v1(9555.12,3602.36) U5.K3@9574.8,3582.68
  MidLayer1 w5: v1(7464.57,3610.24) 7464.57,3633.86 7535.43,3704.73 7685.04,3704.73 7708.66,3681.1 8204.72,3681.1 8299.21,3586.61 9283.46,3586.61 9347.95,3651.1 9486.03,3651.1 9534.77,3602.36 v1(9555.12,3602.36)
DAU_PROG.DONE: HDR_T1.74 U5.N3 | length 2125.2
  Top Layer w7.87: HDR_T1.74@7622.05,3531.5 v1(7622.05,3633.86) ; v1(9555.12,3484.25) U5.N3@9574.8,3464.57
  MidLayer1 w5: v1(7622.05,3633.86) 7677.17,3633.86 7688.98,3622.05 8181.1,3622.05 8275.59,3527.56 9099.38,3527.56 9142.69,3484.25 9413.39,3484.25 9433.07,3484.25 v1(9555.12,3484.25)
DAU_PROG.ID0: HDR_T1.42 U5.C4 | length 2846.2
  Top Layer w7.87: HDR_T1.42@7118.11,3531.5 v1(7118.11,3633.86) ; v1(9594.49,3877.95) U5.C4@9614.17,3858.27
  MidLayer1 w5: v1(7118.11,3633.86) 7500,4015.75 9165.35,4015.75 9312.83,3868.27 9466.63,3868.27 9496,3897.64 9574.8,3897.64 v1(9594.49,3877.95)
DAU_PROG.ID1: HDR_T1.40 U5.C5 | length 3150
  Top Layer w7.87: HDR_T1.40@7086.61,3531.5 v1(7086.61,3610.24) ; v1(9633.86,3877.95) U5.C5@9653.54,3858.27
  MidLayer1 w5: v1(7086.61,3610.24) 7086.61,3641.73 7472.44,4027.56 9185.76,4027.56 9300.2,4142 9622.6,4142 9633.86,4130.74 v1(9633.86,3877.95)
DAU_PROG.ID2: HDR_T1.38 U5.D6 | length 3251.7
  Top Layer w7.87: HDR_T1.38@7055.12,3531.5 v1(7055.12,3633.86) ; v1(9673.23,3838.58) U5.D6@9692.91,3818.9
  MidLayer1 w5: v1(7055.12,3633.86) 7460.63,4039.37 9183.43,4039.37 9296.06,4152 9631.14,4152 9653.54,4129.6 9653.54,3858.27 v1(9673.23,3838.58)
